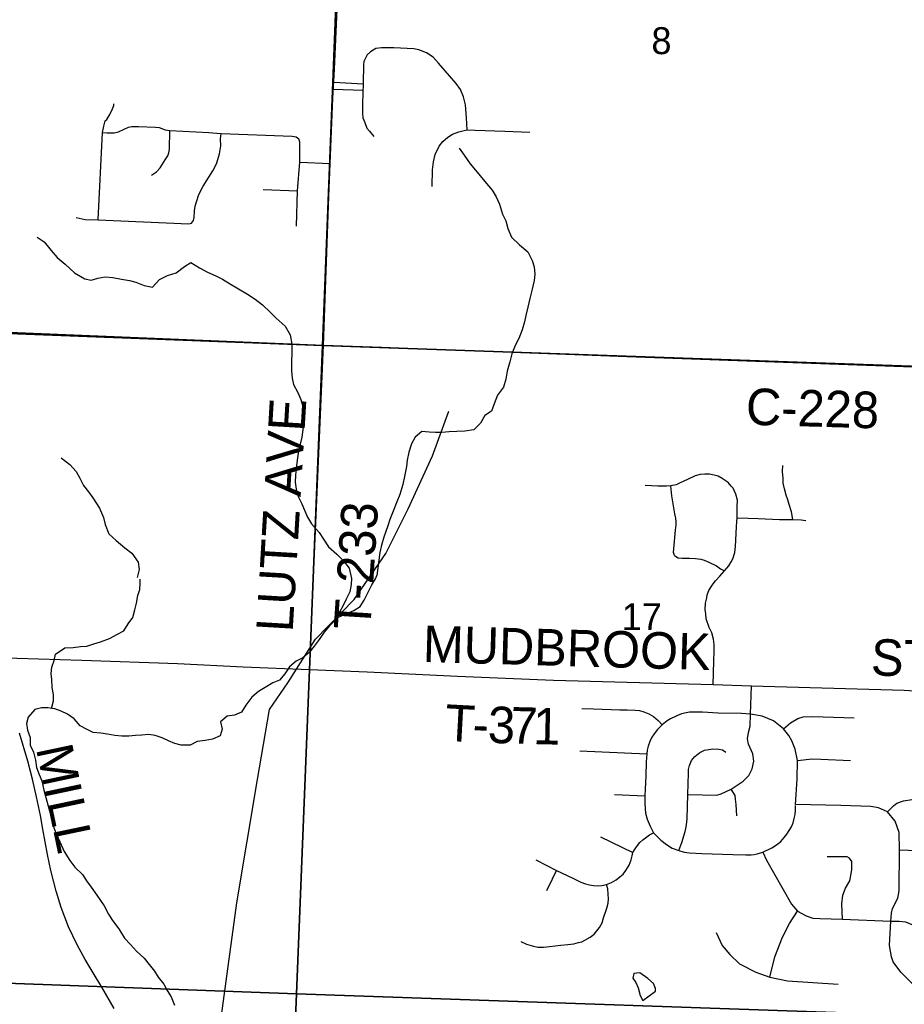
# Model space of a CAD drawing. Extents: x 0 to 34, y 0 to 22.
# Drawn here: x 3.793 to 5.169, y 17.972 to 19.503 of the extents above; entities that cross this region are included whole.
import ezdxf

# ---------------------------------------------------------------- set-up
doc = ezdxf.new("R2010")
doc.units = 0
for name, color, linetype in [('GM_X_Corporation', 7, 'Continuous'), ('GM_X_County_Road', 7, 'Continuous'), ('GM_X_County_Road_Text', 7, 'Continuous'), ('GM_X_Minor_Lake', 7, 'Continuous'), ('GM_X_Minor_River', 7, 'Continuous'), ('GM_X_Rail_Line', 7, 'Continuous'), ('GM_X_Section_Text', 7, 'Continuous'), ('GM_X_Township_Road', 7, 'Continuous'), ('GM_X_Township_Road_Text', 7, 'Continuous')]:
    doc.layers.add(name, color=color, linetype=linetype)

msp = doc.modelspace()

# ---------------------------------------------------------------- linework, layer by layer
at = {"layer": 'GM_X_Corporation'}
for points in [[(4.3035, 20.0005), (4.2642, 18.9963), (3.2335, 19.0353), (3.277, 20.0368)], [(4.3035, 20.0005), (5.3173, 19.9675), (5.2829, 18.9603), (4.2642, 18.9963)], [(3.2335, 19.0353), (4.2642, 18.9963), (4.2238, 17.9879), (3.1939, 18.0257)], [(5.2829, 18.9603), (5.2412, 17.9526), (4.2238, 17.9879), (4.2642, 18.9963)], [(3.1939, 18.0257), (4.2238, 17.9879), (4.1823, 16.9818), (3.1533, 17.0117), (3.155, 17.0299)], [(4.2238, 17.9879), (5.2412, 17.9526), (5.2034, 16.9522), (4.1823, 16.9818)]]:
    msp.add_lwpolyline(points, close=True, dxfattribs=at)
at = {"layer": 'GM_X_County_Road'}
for points in [[(3.3299, 19.0351), (3.4202, 19.0314), (3.5515, 19.0261), (4.2655, 18.9966), (4.3563, 18.9933), (4.4885, 18.9883), (4.6568, 18.982), (4.7374, 18.979), (5.2825, 18.9592)], [(3.9402, 17.9653), (3.9208, 17.9981), (3.9072, 18.0207), (3.8951, 18.0411), (3.8824, 18.0641), (3.8691, 18.0919), (3.8577, 18.1223), (3.8497, 18.1475), (3.8417, 18.1798), (3.8366, 18.2045), (3.8294, 18.2442), (3.8253, 18.2654), (3.8193, 18.2944), (3.813, 18.3216), (3.8056, 18.3498), (3.7929, 18.3934)]]:
    msp.add_lwpolyline(points, dxfattribs=at)
at = {"layer": 'GM_X_Minor_Lake'}
for points in [[(4.7822, 17.9918), (4.7822, 17.9963), (4.7788, 18.0039), (4.77, 18.0115), (4.7574, 18.0205), (4.7483, 18.0197), (4.7469, 18.0121), (4.7514, 18.0057), (4.7549, 17.9974), (4.7584, 17.9852), (4.7622, 17.9776)], [(4.7622, 17.9776), (4.7822, 17.9918)]]:
    msp.add_lwpolyline(points, dxfattribs=at)
at = {"layer": 'GM_X_Minor_River'}
for points in [[(4.4767, 19.3028), (4.4844, 19.2919), (4.4937, 19.2787), (4.5044, 19.2655), (4.5168, 19.2512), (4.5279, 19.2377), (4.5341, 19.2271), (4.5396, 19.2158), (4.5443, 19.2006), (4.549, 19.19), (4.5525, 19.1779), (4.558, 19.1647), (4.5703, 19.1526), (4.5833, 19.1418), (4.5903, 19.1285), (4.5934, 19.1183), (4.5943, 19.1069), (4.5933, 19.097), (4.59, 19.0837), (4.5864, 19.0692), (4.5835, 19.0559), (4.5802, 19.0426), (4.5784, 19.033), (4.5744, 19.0205), (4.5696, 19.0071), (4.564, 18.996), (4.5588, 18.9831), (4.5552, 18.9705), (4.5515, 18.956), (4.549, 18.9438), (4.5457, 18.9312), (4.5363, 18.919), (4.5312, 18.9052), (4.5267, 18.8938), (4.5166, 18.8872), (4.5098, 18.8754), (4.4997, 18.865), (4.4853, 18.863), (4.4728, 18.8624), (4.461, 18.8619), (4.4496, 18.861), (4.4397, 18.8606), (4.4302, 18.8616), (4.4188, 18.8622), (4.4083, 18.8538), (4.4027, 18.8434), (4.3986, 18.8301), (4.3957, 18.8179), (4.3947, 18.808), (4.3914, 18.7924), (4.3889, 18.7798), (4.3845, 18.7646), (4.3797, 18.7528), (4.3738, 18.7386), (4.369, 18.7253), (4.3657, 18.7158), (4.3594, 18.6982), (4.3559, 18.6856), (4.3535, 18.6744), (4.3485, 18.6384)], [(3.8205, 19.1646), (3.8312, 19.1571), (3.842, 19.1439), (3.8512, 19.133), (3.8639, 19.1225), (3.8785, 19.109), (3.8945, 19.0997), (3.9041, 19.0979), (3.9147, 19.101), (3.926, 19.1031), (3.9378, 19.1017), (3.9515, 19.0995), (3.9641, 19.097), (3.974, 19.0948), (3.9866, 19.0893), (3.9995, 19.0868), (4.0108, 19.0987), (4.0229, 19.1049), (4.0365, 19.1092), (4.0497, 19.1192), (4.0595, 19.125), (4.0729, 19.1168), (4.0852, 19.1101), (4.0981, 19.1046), (4.1084, 19.0994), (4.1195, 19.0926), (4.1337, 19.084), (4.1475, 19.0758), (4.1593, 19.068), (4.1708, 19.0594), (4.1827, 19.0481), (4.1923, 19.0387), (4.2058, 19.0263), (4.2139, 19.0127), (4.2163, 18.9983), (4.2165, 18.9835), (4.2159, 18.9717), (4.216, 18.9565), (4.2169, 18.9455), (4.2189, 18.9357), (4.2255, 18.9232), (4.2306, 18.9119), (4.2333, 18.9012), (4.235, 18.891), (4.2355, 18.8808), (4.2341, 18.869), (4.232, 18.8537), (4.2291, 18.8408), (4.2265, 18.8286), (4.2248, 18.8176), (4.2234, 18.805), (4.2223, 18.7947), (4.2217, 18.7837), (4.223, 18.7727), (4.2269, 18.7602), (4.232, 18.75), (4.2359, 18.7402), (4.2409, 18.7292), (4.2471, 18.719), (4.259, 18.7051), (4.2656, 18.6949), (4.2733, 18.6832), (4.2864, 18.6716), (4.2968, 18.6611), (4.3055, 18.6498), (4.3091, 18.6338)], [(3.8577, 18.8212), (3.8711, 18.8111), (3.8811, 18.8001), (3.8869, 18.7899), (3.8923, 18.7786), (3.9004, 18.7688), (3.907, 18.759), (3.9171, 18.7432), (3.9233, 18.7284), (3.9261, 18.7178), (3.9319, 18.7034), (3.9431, 18.6929), (3.9569, 18.6817), (3.9676, 18.673), (3.9776, 18.6591), (3.9789, 18.6477), (3.976, 18.6351)], [(4.2862, 18.5727), (4.3127, 18.5841), (4.3229, 18.5902), (4.329, 18.6001), (4.335, 18.6127), (4.341, 18.6237), (4.3466, 18.6332), (4.3485, 18.6384)], [(4.3091, 18.6338), (4.3087, 18.6243), (4.3065, 18.6129), (4.3009, 18.6015), (4.2964, 18.5916), (4.2907, 18.5814), (4.2851, 18.5707), (4.2749, 18.5601), (4.2666, 18.5505), (4.2591, 18.5387), (4.2512, 18.5285), (4.2433, 18.5186), (4.2334, 18.5106), (4.2232, 18.5052), (4.213, 18.4964), (4.2055, 18.4854), (4.1972, 18.4755), (4.187, 18.4713), (4.1749, 18.4644), (4.1647, 18.4583), (4.1541, 18.4491), (4.1451, 18.437), (4.1379, 18.4259), (4.1273, 18.4213), (4.1156, 18.4198), (4.1054, 18.411), (4.1081, 18.3996), (4.1047, 18.389), (4.093, 18.384), (4.0816, 18.3817), (4.0691, 18.3801), (4.0581, 18.3748), (4.0441, 18.3747), (4.0346, 18.377), (4.0244, 18.3811), (4.0148, 18.386), (4.0038, 18.3897), (3.994, 18.3912), (3.983, 18.3904), (3.9735, 18.3896), (3.9629, 18.3885), (3.9519, 18.3888), (3.9409, 18.3895), (3.9295, 18.3917), (3.9196, 18.3932), (3.9075, 18.3943), (3.898, 18.3992), (3.8874, 18.4049), (3.8778, 18.4155), (3.8676, 18.4226), (3.8577, 18.4275), (3.8478, 18.4309), (3.8368, 18.4328), (3.8269, 18.4327), (3.8167, 18.43), (3.8062, 18.4182), (3.8039, 18.4084), (3.8051, 18.3981), (3.8097, 18.3867), (3.8094, 18.3746), (3.8147, 18.3636), (3.8175, 18.3515), (3.8194, 18.3401), (3.8236, 18.3291), (3.8275, 18.3189), (3.8306, 18.3048), (3.8352, 18.2874), (3.8387, 18.276), (3.8414, 18.265), (3.846, 18.246), (3.851, 18.2347), (3.8556, 18.2241), (3.8621, 18.2093), (3.8713, 18.1953), (3.8789, 18.185), (3.8907, 18.1737), (3.8972, 18.1635), (3.9041, 18.1536), (3.9132, 18.1411), (3.9243, 18.1249), (3.9312, 18.112), (3.9377, 18.1021), (3.9476, 18.0889), (3.9564, 18.0745), (3.9655, 18.0647), (3.9747, 18.0544), (3.9865, 18.0435), (3.9945, 18.0333), (4.0029, 18.0234), (4.0086, 18.0136), (4.0174, 18.003), (4.0224, 17.9931), (4.0288, 17.9833), (4.0338, 17.9704)], [(3.8427, 18.4318), (3.8458, 18.4438), (3.8458, 18.4533), (3.8439, 18.4643), (3.843, 18.4768), (3.8422, 18.4863), (3.8433, 18.4958), (3.8467, 18.5061), (3.8489, 18.5163), (3.8633, 18.5259), (3.8762, 18.5267), (3.8875, 18.5279), (3.8974, 18.5287), (3.9084, 18.5321), (3.919, 18.5352), (3.933, 18.5406), (3.9455, 18.5471), (3.9553, 18.5524), (3.9617, 18.5634), (3.9692, 18.5733), (3.9722, 18.5851), (3.9748, 18.5954), (3.9767, 18.6072), (3.98, 18.6167), (3.9804, 18.6265), (3.9803, 18.6326)]]:
    msp.add_lwpolyline(points, dxfattribs=at)
at = {"layer": 'GM_X_Rail_Line'}
msp.add_lwpolyline([(4.0978, 17.8856), (4.1311, 18.1295), (4.1629, 18.3211), (4.1819, 18.4303), (4.2104, 18.4715), (4.2532, 18.5396), (4.3133, 18.6013), (4.3624, 18.6726), (4.3973, 18.7422), (4.4353, 18.8246), (4.4606, 18.8942)], dxfattribs=at)
at = {"layer": 'GM_X_Township_Road'}
for p, q in [((4.2816, 19.4058), (4.3274, 19.4033)), ((4.281, 19.3947), (4.3267, 19.3933)), ((4.2286, 19.2814), (4.2759, 19.2794)), ((4.1719, 19.2386), (4.2253, 19.2367)), ((4.6641, 18.3656), (4.7683, 18.3613)), ((4.7184, 18.2977), (4.7656, 18.2957)), ((4.6963, 18.2318), (4.7469, 18.2075)), ((5.1616, 18.212), (5.2537, 18.2087))]:
    msp.add_line(p, q, dxfattribs=at)
for points in [[(4.2439, 18.4919), (4.2655, 18.9966), (4.2737, 19.2276), (4.2759, 19.2794), (4.2802, 19.3808), (4.2827, 19.4257), (4.2875, 19.5306), (4.2904, 19.6566), (4.2961, 19.799), (4.2987, 19.8835), (4.3055, 20.0023), (4.3079, 20.0845), (4.3139, 20.2312), (4.3194, 20.3462), (4.3214, 20.4305), (4.3286, 20.6129), (4.3409, 20.9092), (4.3413, 20.9204)], [(4.489, 19.3313), (4.4883, 19.3504), (4.4865, 19.3703), (4.4833, 19.3827), (4.4787, 19.3944), (4.472, 19.4036), (4.4443, 19.4352), (4.4362, 19.4444), (4.4259, 19.4511), (4.4138, 19.4557), (4.4064, 19.4575), (4.3752, 19.4589), (4.3557, 19.4589), (4.3469, 19.4578), (4.3387, 19.4529), (4.3334, 19.4479), (4.3284, 19.438), (4.3277, 19.4327), (4.3277, 19.4235), (4.3274, 19.4132), (4.3274, 19.4033), (4.3274, 19.3983), (4.3267, 19.3933), (4.3263, 19.3675), (4.3263, 19.3575), (4.327, 19.3501), (4.3299, 19.343), (4.333, 19.3341), (4.3373, 19.3292), (4.344, 19.321)], [(3.9151, 19.1918), (3.9219, 19.3273), (3.9241, 19.3374), (3.9263, 19.3453), (3.9285, 19.3477), (3.9336, 19.3554), (3.9377, 19.3641), (3.9396, 19.3695), (3.9396, 19.3717)], [(3.9219, 19.3273), (3.9293, 19.3268), (3.935, 19.3268), (3.9402, 19.3271), (3.9467, 19.3284), (3.9554, 19.3328), (3.9625, 19.3355), (3.9677, 19.3368), (3.978, 19.3368), (4.0044, 19.3355), (4.0101, 19.3352), (4.0196, 19.3314), (4.0265, 19.3306), (4.0872, 19.3276), (4.0929, 19.3268), (4.1063, 19.3257), (4.2168, 19.3215), (4.2229, 19.3206), (4.2275, 19.3174)], [(3.9984, 19.2612), (4.0058, 19.2661), (4.0115, 19.2726), (4.0194, 19.2849), (4.0235, 19.2911), (4.0251, 19.296), (4.0262, 19.3012), (4.0265, 19.3306)], [(4.0604, 19.1864), (4.0636, 19.1905), (4.0643, 19.1951), (4.0649, 19.2058), (4.0662, 19.2127), (4.0679, 19.2194), (4.0716, 19.2307), (4.0783, 19.244), (4.0934, 19.2678), (4.099, 19.2788), (4.1014, 19.2852), (4.1038, 19.2941), (4.1059, 19.3068), (4.1057, 19.3176), (4.1063, 19.3257)], [(4.4348, 19.2434), (4.4351, 19.2693), (4.4365, 19.282), (4.4394, 19.2934), (4.4454, 19.3061), (4.4511, 19.3136), (4.4589, 19.32), (4.4663, 19.3249), (4.4762, 19.3285), (4.4844, 19.3306), (4.489, 19.3313), (4.5014, 19.331), (4.5475, 19.3292), (4.5864, 19.3278)], [(4.2236, 19.1819), (4.2253, 19.2367), (4.2286, 19.2814), (4.2288, 19.3124), (4.2275, 19.3174)], [(3.8808, 19.1953), (3.895, 19.1923), (3.9151, 19.1918), (4.0563, 19.1851), (4.0604, 19.1864)], [(4.9954, 18.7257), (4.9933, 18.7374), (4.9899, 18.7491), (4.988, 18.7563), (4.9851, 18.7633), (4.9825, 18.7731), (4.9808, 18.7822), (4.9803, 18.7894), (4.9796, 18.8002), (4.9799, 18.8093)], [(4.8999, 18.7776), (4.895, 18.7831), (4.8857, 18.7895), (4.8793, 18.7927), (4.8732, 18.7946), (4.8662, 18.7962), (4.8585, 18.7962), (4.8517, 18.7956), (4.8437, 18.7937), (4.8319, 18.7876), (4.8203, 18.7824), (4.8142, 18.7796), (4.8056, 18.778), (4.7989, 18.7776), (4.7854, 18.7776), (4.7658, 18.7786)], [(4.8115, 18.6694), (4.8098, 18.6742), (4.8103, 18.6797), (4.8131, 18.7087), (4.8139, 18.7175), (4.8139, 18.7221), (4.8134, 18.7276), (4.8122, 18.7345), (4.8074, 18.7623), (4.8056, 18.778)], [(4.8719, 18.4684), (4.8729, 18.5052), (4.8732, 18.5206), (4.8735, 18.5309), (4.8722, 18.5395), (4.8697, 18.5492), (4.8655, 18.5578), (4.861, 18.5713), (4.8604, 18.5786), (4.8594, 18.5854), (4.8597, 18.5953), (4.8617, 18.6039), (4.8626, 18.6084), (4.8652, 18.6152), (4.8687, 18.6206), (4.8716, 18.6254), (4.8754, 18.6299), (4.8822, 18.6376), (4.8895, 18.6456), (4.8963, 18.6533), (4.8998, 18.6597), (4.9024, 18.6645), (4.9052, 18.6744), (4.9065, 18.6834), (4.9078, 18.7139), (4.9084, 18.7222), (4.9088, 18.7283), (4.9091, 18.7456), (4.9097, 18.7555), (4.9069, 18.7651), (4.9027, 18.7744), (4.8999, 18.7776)], [(4.9088, 18.7283), (4.926, 18.7278), (4.9418, 18.7269), (4.9748, 18.7254), (4.987, 18.7257), (4.9954, 18.7257), (5.0086, 18.7252), (5.0158, 18.724)], [(4.8115, 18.6694), (4.8175, 18.666), (4.8235, 18.6656), (4.8349, 18.6656), (4.8443, 18.6648), (4.8527, 18.6639), (4.8577, 18.6622), (4.8651, 18.6593), (4.8769, 18.6533), (4.8831, 18.649), (4.8895, 18.6456)], [(5.2718, 18.4356), (5.2631, 18.4401), (5.2447, 18.4477), (5.2197, 18.4549), (5.194, 18.4582), (5.169, 18.4595), (4.9315, 18.4661), (4.8719, 18.4684), (4.6236, 18.4752), (4.4743, 18.4812), (4.3338, 18.4879), (4.2439, 18.4919), (4.1405, 18.4961), (4.0385, 18.501), (3.8897, 18.5061), (3.7543, 18.5105)], [(4.8325, 18.298), (4.8775, 18.297), (4.8843, 18.2991), (4.8997, 18.3063), (4.9185, 18.3188), (4.9274, 18.3274), (4.9326, 18.3379), (4.9349, 18.3497), (4.9333, 18.3612), (4.9267, 18.376), (4.9251, 18.3846), (4.9267, 18.3944), (4.929, 18.404), (4.93, 18.423), (4.9315, 18.4661)], [(4.6675, 18.4314), (4.6857, 18.431), (4.7264, 18.4298), (4.738, 18.4296), (4.7504, 18.4292), (4.7569, 18.4284), (4.7637, 18.4264), (4.7717, 18.4234), (4.7787, 18.419), (4.7863, 18.4128), (4.7923, 18.4061)], [(4.9997, 18.2823), (5.0022, 18.3215), (5.0026, 18.351), (4.9994, 18.3685), (4.9941, 18.3813), (4.9895, 18.3895), (4.9809, 18.4), (4.9734, 18.4063), (4.9655, 18.4122), (4.9477, 18.4198), (4.93, 18.423), (4.9157, 18.4237), (4.8794, 18.4244), (4.8552, 18.4257), (4.8421, 18.4257), (4.8349, 18.4257), (4.8299, 18.4249), (4.8224, 18.4231), (4.8152, 18.4204), (4.8054, 18.4154), (4.8001, 18.4123), (4.7923, 18.4061), (4.7852, 18.399), (4.7797, 18.3922), (4.7761, 18.3868), (4.773, 18.3802), (4.7707, 18.3729), (4.7691, 18.3668), (4.7683, 18.3613), (4.7674, 18.3487), (4.7668, 18.3266), (4.7661, 18.3062), (4.7656, 18.2957), (4.7653, 18.284), (4.7658, 18.2761), (4.7666, 18.2691), (4.7692, 18.2596), (4.7735, 18.2488), (4.7789, 18.2385), (4.7854, 18.2317), (4.7903, 18.2271), (4.799, 18.2199), (4.8078, 18.2145), (4.8181, 18.2107), (4.8264, 18.2083), (4.8348, 18.207), (4.8539, 18.2063), (4.9023, 18.2047), (4.9224, 18.204), (4.9306, 18.2042), (4.9356, 18.2048), (4.9399, 18.2055), (4.949, 18.2081), (4.9629, 18.2148), (4.9701, 18.2197), (4.9767, 18.2249), (4.9819, 18.2312), (4.9861, 18.2362), (4.9899, 18.2418), (4.9935, 18.2477), (4.9959, 18.2536), (4.9979, 18.2606), (4.9991, 18.267), (4.9995, 18.2733), (4.9997, 18.2807)], [(4.9809, 18.4), (4.9921, 18.4092), (5.0033, 18.4161), (5.0115, 18.4188), (5.0267, 18.4194), (5.0908, 18.4171)], [(4.8181, 18.2107), (4.8228, 18.2232), (4.8281, 18.2402), (4.8293, 18.2452), (4.8304, 18.2506), (4.8312, 18.2601), (4.8325, 18.298), (4.8331, 18.3313), (4.8335, 18.3367), (4.8351, 18.3428), (4.8382, 18.351), (4.843, 18.3571), (4.851, 18.3633), (4.8584, 18.3669), (4.8651, 18.3681), (4.8713, 18.3689), (4.8806, 18.3686), (4.8864, 18.3674), (4.8912, 18.3638)], [(5.143, 18.2708), (5.1519, 18.28), (5.1575, 18.2843), (5.1677, 18.2882), (5.1809, 18.2902), (5.1924, 18.2895), (5.1993, 18.2895), (5.2049, 18.2915), (5.2082, 18.2961), (5.2091, 18.305), (5.2114, 18.3619)], [(5.0026, 18.351), (5.0257, 18.3533), (5.0391, 18.353), (5.0855, 18.3507)], [(4.9086, 18.2649), (4.9073, 18.2823), (4.9066, 18.2905), (4.9057, 18.2961), (4.8997, 18.3063)], [(5.1948, 17.8534), (5.198, 17.9556), (5.197, 17.9721), (5.192, 17.9872), (5.1822, 18.0027), (5.1638, 18.0217), (5.1516, 18.0375), (5.1493, 18.0454), (5.1457, 18.0632), (5.148, 18.101), (5.1491, 18.1133), (5.1508, 18.1205), (5.1588, 18.1367), (5.1611, 18.148), (5.1616, 18.212), (5.1608, 18.2389), (5.1549, 18.2563), (5.143, 18.2708), (5.1286, 18.2771), (5.1167, 18.279), (5.0704, 18.281), (4.9997, 18.2823)], [(4.5958, 18.1962), (4.6282, 18.1795), (4.6536, 18.168), (4.6658, 18.1618), (4.6732, 18.159), (4.6792, 18.1575), (4.6856, 18.1565), (4.6918, 18.1558), (4.6984, 18.1565), (4.7057, 18.1579), (4.7134, 18.1612), (4.7206, 18.1652), (4.7266, 18.1697), (4.7317, 18.1742), (4.736, 18.1795), (4.7409, 18.1878), (4.7441, 18.1962), (4.7458, 18.2024), (4.7469, 18.2075), (4.7503, 18.2132), (4.7539, 18.2188), (4.7576, 18.2231), (4.7623, 18.2275), (4.7727, 18.235), (4.7789, 18.2385)], [(4.949, 18.2081), (4.9546, 18.1958), (4.9933, 18.1272), (5.0026, 18.1163), (5.0161, 18.109), (5.0267, 18.1057), (5.0375, 18.1051), (5.073, 18.1041), (5.148, 18.101), (5.161, 18.101), (5.1709, 18.0999), (5.1897, 18.0921), (5.1971, 18.0865), (5.2022, 18.0791)], [(5.073, 18.1041), (5.072, 18.1278), (5.0733, 18.1413), (5.0776, 18.1524), (5.0845, 18.1636), (5.0872, 18.1807), (5.0872, 18.1935), (5.0839, 18.1988), (5.0802, 18.2011), (5.049, 18.2011)], [(4.613, 18.1484), (4.6219, 18.1665), (4.6282, 18.1795)], [(4.5724, 18.0695), (4.5816, 18.0652), (4.5922, 18.062), (4.5989, 18.0607), (4.608, 18.0605), (4.617, 18.0616), (4.6349, 18.0637), (4.6454, 18.0646), (4.6548, 18.0656), (4.662, 18.0675), (4.6674, 18.069), (4.6723, 18.0712), (4.6802, 18.0759), (4.6864, 18.0806), (4.6909, 18.0861), (4.6949, 18.091), (4.699, 18.0985), (4.7013, 18.106), (4.7062, 18.1209), (4.7084, 18.129), (4.7088, 18.1356), (4.7086, 18.1431), (4.7077, 18.1514), (4.7057, 18.1579)], [(4.9596, 18.014), (4.9678, 18.0452), (4.9796, 18.0762), (4.9905, 18.0972), (5.0026, 18.1163)], [(4.8761, 18.0834), (4.8859, 18.0633), (4.8974, 18.0492), (4.9129, 18.0347), (4.9379, 18.0216), (4.9596, 18.014), (4.9872, 18.0081), (5.0661, 18.0028)]]:
    msp.add_lwpolyline(points, dxfattribs=at)

# ---------------------------------------------------------------- texts
at = {"layer": 'GM_X_County_Road_Text'}
for s, height, rotation, p in [('C-228', 0.05682, 358.3476, (4.9221, 18.873)), ('M', 0.0568, 281.957, (3.8183, 18.3695)), ('I', 0.0568, 281.9597, (3.831, 18.3091)), ('L', 0.0568, 281.958, (3.8359, 18.2863)), ('L', 0.0568, 281.8092, (3.8447, 18.2448))]:
    msp.add_text(s, height=height, rotation=rotation, dxfattribs=at).set_placement(p)
at = {"layer": 'GM_X_Section_Text'}
for s, height, p in [('8', 0.0419, (4.7757, 19.4492)), ('17', 0.04186, (4.7295, 18.5535))]:
    msp.add_text(s, height=height, rotation=0, dxfattribs=at).set_placement(p)
at = {"layer": 'GM_X_Township_Road_Text'}
for s, height, rotation, p in [('LUTZ AVE', 0.05682, 86.6089, (4.2176, 18.5496)), ('T-233', 0.05682, 86.3536, (4.3383, 18.5529)), ('MUDBROOK', 0.05682, 358.3615, (4.4197, 18.504)), ('ST', 0.05682, 358.2167, (5.1165, 18.4832)), ('T', 0.0568, 356.9086, (4.4534, 18.3815)), ('3', 0.0568, 358.2385, (4.5206, 18.3783)), ('7', 0.0568, 358.6226, (4.556, 18.3772)), ('1', 0.0568, 358.721, (4.5911, 18.3763)), ('-', 0.0568, 357.8197, (4.4968, 18.3792))]:
    msp.add_text(s, height=height, rotation=rotation, dxfattribs=at).set_placement(p)

doc.saveas('drawing.dxf')
